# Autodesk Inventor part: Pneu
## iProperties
Created: 2002-04
Part Number: Pneu
Material: Par défaut
Document SubType Name: Modélisation
Designer: Flavien MARTY
Control State: 0
Master: False
Checked Out: False
Shininess: 20.0
Length Units: 11269
Angle Units: 11279
Time Units: 11290
Mass Units: 11283
Length Display Precision: 3
Angle Display Precision: 2
Compacted: True
Density: 0.0
Volumn: 0.0
Area: 0.0
PropertySet Name: Model Information
Author: Flavien MARTY
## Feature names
1. Révolution1 [Revolution]
